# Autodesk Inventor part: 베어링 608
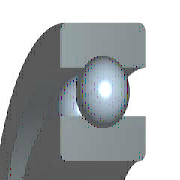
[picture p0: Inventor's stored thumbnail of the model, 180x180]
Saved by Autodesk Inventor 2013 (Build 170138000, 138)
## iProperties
IsCustomPart: 1
Created: 2012-02
Part Number: 베어링 608
Material: 강철, 연강
Description: 깊은 그루브 볼 베어링
Document SubType Name: Modeling
Standard: KS B 2023
Designer: mduedu
Standards Organization: KS
Language: ko-KR
Size Designation: 608 - 8 x 22 x 7
Categories: <MemberInstance><Categories><Category DisplayName="샤프트 부품" InternalName="7f7aeb1f-a693-4053-b835-cee3144e0d98" Mnemonic="SHFT"><Category DisplayName="베어링" Inter
Density: 7.86 g/cm^3
Mass: 12.1605 g
Surface Area: 20.0754 cm^2
Volume: 1.54714 cm^3
Author: mduedu
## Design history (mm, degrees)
sketch "스케치" dims "d0" = 3.64 (= -0.26 x WD + 0.26 x BD)
  geometry: L1 (1.68, 7.5)-(5.32, 7.5); L2 (3.5, 7.5)-(3.5, 5.68); L3 (3.5, 7.5)-(3.5, 9.32); L4 (2.148, 6.282)-(0, 6.282); L5 (0, 4)-(7, 4); L6 (2.148, 8.718)-(0, 8.718); L7 (0, 11)-(7, 11); L8 (7, 4)-(7, 6.282); L9 (4.852, 6.282)-(7, 6.282); L10 (4.852, 8.718)-(7, 8.718); L11 (7, 11)-(7, 8.718); L12 (-1.4, 0)-(8.4, 0) reference; L13 (0, -0.3)-(0, 5.3) reference
  constraints: 22 end point, 4 point on line, 2 collinear, 2 perpendicular, 2 symmetric about line, 1 midpoint, 1 parallel, 14 other
  dimensions: "d9" = 8 diameter of L5 L12 (= WD); "d11" = 22 diameter of L7 L12 (= BD); "d12" = 7 distance between parallel lines of L8 L13 (= KB); "d13" = 12.564 diameter of L9 L12 (= 0.326 x BD + 0.674 x WD)
revolve "본체" stored, may be unused: angle "d6" = 90 deg
revolve "볼" stored, may be unused: angle "d7" = 90 deg
pattern_circular "IDS_ARRAYBALL[SIMPL:T]" dims angle "d3" = 360 deg
body "Solid1"
fillet "모깎기1" dims "d1" = 0.3 (= KRS)
other parameters: "WD" = 8 [user parameter; used in 5 equation terms], "BD" = 22 [user parameter; used in 5 equation terms], "KB" = 7 [user parameter; used in 1 equation term], "KRS" = 0.3 [user parameter; used in 1 equation term], "d4" = 0, "d5" = 0, "d8" = 0, "d14" = 0, "d15" = 0, "BBA" = 0 [user parameter], "BC0" = 1370000 [user parameter], "BC" = 3250000 [user parameter], "BR" = 11 (= 0.5 x BD) [user parameter], "WR" = 4 (= 0.5 x WD) [user parameter]
